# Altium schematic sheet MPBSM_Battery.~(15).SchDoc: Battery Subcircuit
size A3; Date: Not shown in title block; ApprovedBy: Not shown in title block; CheckedBy: Not shown in title block; Author: Not shown in title block; CompanyName: Not shown in title block; DrawnBy: Not shown in title block; Engineer: Not shown in title block; Organization: Not shown in title block; Address1: Not shown in title block; Address2: Not shown in title block; Address3: Not shown in title block; Address4: Not shown in title block; DocumentNumber: 3; Revision: Use project parameter SCH_Rev; SheetNumber: 3; SheetTotal: 12; PageSetup: Record=PageOptions¦CenterHorizontal=True¦CenterVertical=True¦PrintScale=0.69¦XCorrection=1.00¦YCorrection=1.00¦PrintKind=0¦BorderSize=5000000¦LeftOffset=0¦BottomOffset=0¦Orientation=2¦PaperLength=1000¦PaperWidth=1000¦Scale=100¦PaperSource=15¦PrintQuality=600¦MediaType=1¦DitherType=10¦PaperKind=Letter¦PrintScaleMode=1
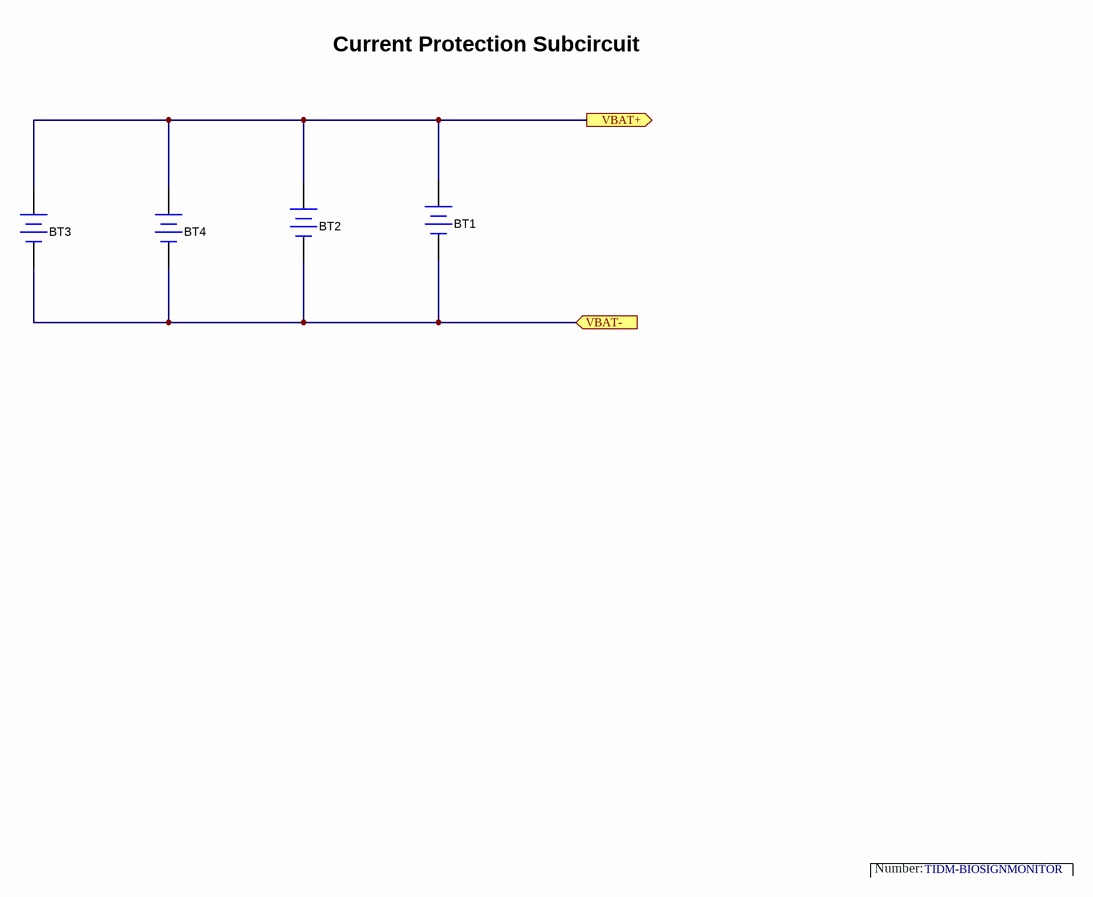
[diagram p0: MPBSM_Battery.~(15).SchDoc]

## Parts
BT1  XXXXXX  [Flat_Battery]  (value not drawn)
BT2  XXXXXX  [Flat_Battery]  (value not drawn)
BT3  2462  [Keystone_2462]  (value not drawn)
BT4  2462  [Keystone_2462]  (value not drawn)

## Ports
VBAT+ (out), VBAT- (in)

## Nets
VBAT+: BT1.1(+) BT2.1(+) BT3.1(+) BT4.1(+) ; port VBAT+
VBAT-: BT1.2(-) BT2.2(-) BT3.2(-) BT4.2(-) ; port VBAT-

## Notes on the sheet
- Current Protection Subcircuit
- Number:
- TIDM-BIOSIGNMONITOR

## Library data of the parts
BT1 = Battery: Battery, Lithium Polymer, 3V, 25mAh; Manufacturer: Solicore; U/M: EA; Value: 3 Volts; TaMax_C: 60° C; TaMin_C: -10° C; Value1: 10mAh to 28mAh; Value2: Ultra-thin: 0.37mm – 0.45mm; SymbolCreator: a0272897
BT2 = Battery: Battery, Lithium Polymer, 3V, 25mAh; Manufacturer: Solicore; U/M: EA; Value: 3 Volts; Capacity: 10mAh to 28mAh; TaMax_C: 60° C; TaMin_C: -10° C; Value2: Ultra-thin: 0.37mm – 0.45mm; SymbolCreator: a0272897
BT3 BT4 = 2462: 2x AA Battery Holder, Through-hole mount; Manufacturer: Keystone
